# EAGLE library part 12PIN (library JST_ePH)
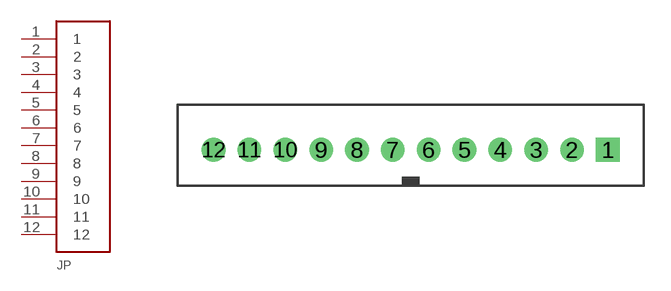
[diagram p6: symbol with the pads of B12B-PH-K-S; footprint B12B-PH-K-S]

Designator prefix JP

## 12PIN  [B12B-PH-K-S]
1  1
2  2
3  3
4  4
5  5
6  6
7  7
8  8
9  9
10  10
11  11
12  12

## Footprint B12B-PH-K-S (pad centres in mm)
drill 0.813 square: 1 11,0
drill 0.813 round: 2 9,0; 3 7,0; 4 5,0; 5 3,0; 6 1,0; 7 -1,0; 8 -3,0; 9 -5,0; 10 -7,0; 11 -9,0; 12 -11,0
